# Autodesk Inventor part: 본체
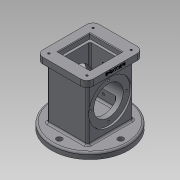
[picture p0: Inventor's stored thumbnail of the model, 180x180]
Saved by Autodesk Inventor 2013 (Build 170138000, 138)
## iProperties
Created: 2018-10
Part Number: 본체
Material: 일반
Document SubType Name: Modeling
Designer: Administrator
Density: 1 g/cm^3
Author: Administrator
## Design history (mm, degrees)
sketch "스케치1"
  geometry: C1 r 62.5 at (0, 0); 1 further point
  constraints: 1 centre point, 1 coincident
  dimensions: "d0" = 125 diameter of C1
extrude "돌출1" new body sketch "스케치1" distance "d1" = 10; taper "d2" = 0 deg
sketch "스케치2"
  geometry: L1 (-37, -33)-(37, -33); L2 (37, -33)-(37, 33); L3 (37, 33)-(-37, 33); L4 (-37, 33)-(-37, -33); L5 (-37, -33)-(37, 33); L6 (37, -33)-(-37, 33); C1 r 62.5 at (0, 0) reference
  constraints: 12 end point, 2 midpoint, 2 parallel, 1 horizontal, 1 perpendicular
  dimensions: "d3" = 74 distance of L3.end L2.end; "d4" = 66 distance of L2.end L1.end
extrude "돌출2" join sketch "스케치2" distance "d5" = 88; taper "d6" = 0 deg
sketch "스케치3"
  geometry: L1 (-46, -41)-(46, -41); L2 (46, -41)-(46, 41); L3 (46, 41)-(-46, 41); L4 (-46, 41)-(-46, -41); L5 (-46, -41)-(46, 41); L6 (46, -41)-(-46, 41); 1 further point
  constraints: 12 end point, 2 midpoint, 2 parallel, 1 horizontal, 1 perpendicular
  dimensions: "d7" = 92 distance of L3.end L2.end; "d8" = 82 distance of L2.end L1.end
extrude "돌출3" join sketch "스케치3" distance "d9" = 10; taper "d10" = 0 deg
sketch "스케치4"
  geometry: L1 (-26, -26)-(26, -26); L2 (26, -26)-(26, 26); L3 (26, 26)-(-26, 26); L4 (-26, 26)-(-26, -26); L5 (-26, -26)-(26, 26); L6 (26, -26)-(-26, 26); 1 further point
  constraints: 12 end point, 2 midpoint, 2 parallel, 1 horizontal, 1 perpendicular
  dimensions: "d11" = 52 distance of L2.end L3.end; "d13" = 52 distance between parallel lines of L1 L3
extrude "돌출4" cut sketch "스케치4" distance "d14" = 8; taper "d15" = 0 deg
sketch "스케치5"
  geometry: L1 (-22, -22)-(22, -22); L2 (22, -22)-(22, 22); L3 (22, 22)-(-22, 22); L4 (-22, 22)-(-22, -22); L5 (-22, -22)-(22, 22); L6 (22, -22)-(-22, 22); 1 further point
  constraints: 12 end point, 2 midpoint, 2 parallel, 1 horizontal, 1 perpendicular
  dimensions: "d16" = 44 distance of L3.end L2.end; "d17" = 44 distance of L2.end L1.end
extrude "돌출5" cut sketch "스케치5" distance "d18" = 74; taper "d19" = 0 deg
fillet "모깎기1" dims "d20" = 3
sketch "스케치6"
  geometry: L1 (13, -33)-(95, -33) reference; L2 (95, 33)-(13, 33) reference; L3 (54, -33)-(54, 33); L4 (89, 33)-(89, 30); L5 (89, 30)-(78, 30); L6 (78, 30)-(78, -30); L7 (78, -30)-(89, -30); L8 (89, -30)-(89, -33); 1 further point
  constraints: 12 end point, 3 parallel, 2 midpoint, 2 perpendicular, 2 point on line
  dimensions: "d21" = 3 distance between parallel lines of L2 L5; "d22" = 3 distance between parallel lines of L1 L7; "d23" = 70 diameter of L4 L3; "d24" = 70 diameter of L8 L3; "d25" = 48 diameter of L6 L3
revolve "회전1" sketch "스케치6" stored, may be unused: angle "d26" = 90 deg
sketch "스케치8"
  geometry: 2 further points
  dimensions: "d30" = 31 vertical distance of point (0, 0) point (36, 31); "d31" = 36 horizontal distance of point (0, 0) point (36, 31)
hole "구멍1" sketch "스케치8" at (36, 31) diameter "d32" = 3.242; stored, may be unused: countersink angle "d36" = 90 deg, drill point angle "d38" = 118 deg; dims "d33" = 4, "d34" = 4, "d35" = 2, "d37" = 6
sketch "스케치9"
  geometry: L1 (-62.5, 0)-(62.5, 0) reference; L2 (-28, 0)-(-24.826, 18); L3 (0, 0)-(0, 18); L4 (0, 18)-(-24.826, 18)
  constraints: 6 end point, 2 perpendicular, 1 midpoint, 1 point on line
  dimensions: "d43" = 80 deg angle of L1 L2; "d45" = 18 distance of L3.start L3.end; "d46" = 56 diameter of L2.start L3
revolve "회전2" sketch "스케치9" stored, may be unused: angle "d47" = 90 deg
sketch "스케치10"
  geometry: C1 r 35 at (0, 0) reference; 2 further points
  constraints: 1 horizontal alignment
  dimensions: "d48" = 29 distance of point (29, 0) C1.centre
hole "구멍2" sketch "스케치10" at (29, 0) diameter "d49" = 3.242; stored, may be unused: countersink angle "d53" = 90 deg, drill point angle "d55" = 118 deg; dims "d50" = 4, "d51" = 4, "d52" = 2, "d54" = 6
sketch "스케치13"
  geometry: L1 (-92.5, -13)-(32.5, -13) reference; 3 further points
  constraints: 1 midpoint, 1 vertical alignment
  dimensions: "d77" = 37 distance from line of L1 point (-30, 24)
hole "구멍5" sketch "스케치13" at (-30, 24) diameter "d78" = 4.134; stored, may be unused: countersink angle "d82" = 90 deg, drill point angle "d84" = 118 deg; dims "d79" = 18, "d80" = 4, "d81" = 2, "d83" = 6
sketch "스케치14"
  geometry: C1 r 2.067 at (-30, 24) reference; 2 further points
  constraints: 1 vertical alignment
  dimensions: "d85" = 43 distance of C1.centre point (-30, 67)
hole "구멍6" sketch "스케치14" at (-30, 67) diameter "d86" = 4.134; stored, may be unused: countersink angle "d90" = 90 deg, drill point angle "d92" = 118 deg; dims "d87" = 18, "d88" = 4, "d89" = 2, "d91" = 6
sketch "스케치15"
  geometry: C1 r 28 at (0, 0) reference; C2 r 4.5 at (0, 50)
  constraints: 1 centre point, 1 vertical alignment
  dimensions: "d93" = 9 diameter of C2; "d94" = 50 distance of C1.centre C2.centre
extrude "돌출7" cut sketch "스케치15" stored distance "d95" = 18; taper "d96" = 0 deg
sketch "스케치16"
  geometry: L1 (0, 10)-(92, 10) reference; L2 (0, 0)-(0, 10) reference; 2 further points
  constraints: 1 other
  dimensions: "d100" = 46 distance from line of L2 point (46, 6); "d101" = 4 distance from line of L1 point (46, 6)
feature "엠보싱1" sketch "스케치16" dims "d102" = 0.5, "d103" = 0
fillet "모깎기2" dims "d104" = 10
fillet "모깎기3" dims "d105" = 3
chamfer "모따기1" distance "d106" = 1; stored, may be unused: second distance "d107" = 2, angle "d108" = 45 deg
fillet "모깎기4" dims "d109" = 3
node "솔리드1"
mirror "대칭1"
mirror "대칭2"
pattern_circular "원형 패턴1" dims angle "d57" = 360 deg
mirror "대칭3"
pattern_circular "원형 패턴2" dims angle "d98" = 360 deg
node "작업 평면1"
node "작업 평면2"
node "작업 평면3"
